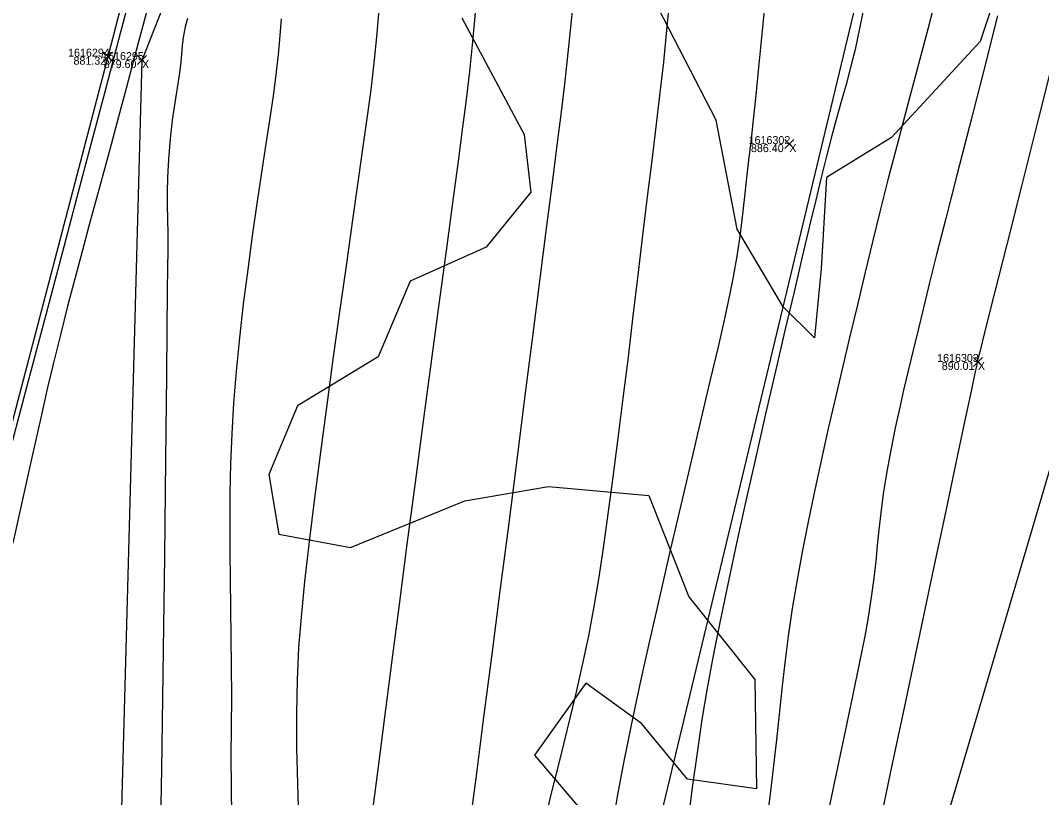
# Model space of a CAD drawing. Extents: x 1957117 to 1971063, y 701601 to 715861.
# Drawn here: x 1963340.46 to 1963385.1, y 706307.76 to 706341.74 of the extents above; entities that cross this region are included whole.
import ezdxf

# ---------------------------------------------------------------- set-up
doc = ezdxf.new("R2010")
doc.units = 0
for name, color, linetype in [('AP_X_Lights', 7, 'Continuous'), ('DT_X_Break_Line', 7, 'Continuous'), ('DT_X_Contour_Major', 7, 'Continuous'), ('DT_X_Contour_Minor', 7, 'Continuous'), ('DT_X_TIN_Hull', 7, 'Continuous'), ('HY_X_Water_Edge', 7, 'Continuous'), ('PV_P_Shoulder', 7, 'Continuous'), ('RS_Raster1', 7, 'Continuous'), ('RW_X_Esmt_RR', 7, 'Continuous'), ('SC_Scratch1', 7, 'Continuous'), ('SC_Shading5', 7, 'Continuous'), ('VG_X_Tree_Line_Rt', 7, 'Continuous')]:
    doc.layers.add(name, color=color, linetype=linetype)

msp = doc.modelspace()

# ---------------------------------------------------------------- linework, layer by layer
at = {"layer": 'AP_X_Lights'}
for p, q in [((1963344.086, 706339.963), (1963344.474, 706340.353)), ((1963344.086, 706340.353), (1963344.474, 706339.963)), ((1963345.578, 706339.814), (1963345.966, 706340.204)), ((1963345.578, 706340.204), (1963345.966, 706339.814)), ((1963373.879, 706336.141), (1963374.267, 706336.531)), ((1963373.879, 706336.531), (1963374.267, 706336.141)), ((1963382.124, 706326.614), (1963382.512, 706327.004)), ((1963382.124, 706327.004), (1963382.512, 706326.614))]:
    msp.add_line(p, q, dxfattribs=at)
at = {"layer": 'DT_X_Break_Line'}
for points in [[(1963218.329, 705756.178), (1963229.265, 705808.356), (1963234.8, 705853.147), (1963240.079, 705903.468), (1963258.033, 705954.684), (1963270.287, 705999.321), (1963276.323, 706049.345), (1963291.502, 706096.678), (1963290.138, 706117.655), (1963319.921, 706191.295), (1963330.374, 706242.631), (1963344.413, 706289.409), (1963345.772, 706340.009), (1963383.117, 706434.704), (1963392.11, 706487.426), (1963408.164, 706535.687), (1963423.633, 706582.721), (1963435.242, 706630.63), (1963443.084, 706680.696), (1963464.732, 706726.815), (1963480.654, 706774.214), (1963508.465, 706799.669), (1963511.002, 706809.48)], [(1963248.355, 705747.376), (1963261.829, 705795.923), (1963267.581, 705840.559), (1963287.153, 705892.264), (1963291.083, 705944.763), (1963301.574, 705996.211), (1963311.528, 706039.027), (1963334.717, 706086.75), (1963331.957, 706106.508), (1963348.786, 706182.796), (1963365.664, 706223.934), (1963373.462, 706281.461), (1963387.853, 706330.217), (1963397.264, 706379.501), (1963407.696, 706427.592), (1963426.755, 706477.16), (1963442.136, 706524.014), (1963446.007, 706569.971), (1963489.391, 706666.839), (1963500.526, 706701.536)]]:
    msp.add_lwpolyline(points, dxfattribs=at)
at = {"layer": 'DT_X_Contour_Major'}
for points in [[(1963368.885, 706343.098), (1963368.724, 706341.474), (1963368.565, 706339.921), (1963368.404, 706338.455), (1963368.241, 706337.093), (1963368.057, 706335.622), (1963367.863, 706334.034), (1963367.661, 706332.355), (1963367.452, 706330.609), (1963367.238, 706328.822), (1963367.021, 706327.02), (1963366.801, 706325.229), (1963366.581, 706323.472), (1963366.362, 706321.777), (1963366.145, 706320.169), (1963365.933, 706318.672), (1963365.727, 706317.313), (1963365.528, 706316.116), (1963365.289, 706314.84), (1963365.035, 706313.618), (1963364.769, 706312.438), (1963364.494, 706311.289), (1963364.214, 706310.158), (1963363.932, 706309.032), (1963363.652, 706307.901), (1963363.377, 706306.752)], [(1963368.885, 706343.098), (1963368.724, 706341.474), (1963368.565, 706339.921), (1963368.404, 706338.455), (1963368.241, 706337.093), (1963368.057, 706335.622), (1963367.863, 706334.034), (1963367.661, 706332.355), (1963367.452, 706330.609), (1963367.238, 706328.822), (1963367.021, 706327.02), (1963366.801, 706325.229), (1963366.581, 706323.472), (1963366.362, 706321.777), (1963366.145, 706320.169), (1963365.933, 706318.672), (1963365.727, 706317.313), (1963365.528, 706316.116), (1963365.289, 706314.84), (1963365.035, 706313.618), (1963364.769, 706312.438), (1963364.494, 706311.289), (1963364.214, 706310.158), (1963363.932, 706309.032), (1963363.652, 706307.901), (1963363.377, 706306.752)], [(1963346.111, 706342.659), (1963345.767, 706341.35), (1963345.421, 706340.044), (1963345.08, 706338.763), (1963344.746, 706337.525), (1963344.418, 706336.319), (1963344.096, 706335.137), (1963343.777, 706333.969), (1963343.462, 706332.805), (1963343.148, 706331.635), (1963342.834, 706330.451), (1963342.52, 706329.242), (1963342.205, 706327.999), (1963341.886, 706326.713), (1963341.645, 706325.695), (1963341.341, 706324.366), (1963340.982, 706322.762), (1963340.575, 706320.921), (1963340.126, 706318.881)], [(1963346.111, 706342.659), (1963345.767, 706341.35), (1963345.421, 706340.044), (1963345.08, 706338.763), (1963344.746, 706337.525), (1963344.418, 706336.319), (1963344.096, 706335.137), (1963343.777, 706333.969), (1963343.462, 706332.805), (1963343.148, 706331.635), (1963342.834, 706330.451), (1963342.52, 706329.242), (1963342.205, 706327.999), (1963341.886, 706326.713), (1963341.645, 706325.695), (1963341.341, 706324.366), (1963340.982, 706322.762), (1963340.575, 706320.921), (1963340.126, 706318.881)], [(1963347.761, 706341.834), (1963347.664, 706341.46), (1963347.575, 706340.998), (1963347.533, 706340.631), (1963347.505, 706340.262), (1963347.456, 706339.79), (1963347.392, 706339.355), (1963347.303, 706338.798), (1963347.201, 706338.137), (1963347.096, 706337.388), (1963347, 706336.565), (1963346.925, 706335.684), (1963346.881, 706334.88), (1963346.868, 706334.224), (1963346.873, 706333.643), (1963346.887, 706333.061), (1963346.897, 706332.404), (1963346.895, 706331.596), (1963346.888, 706331), (1963346.877, 706329.858), (1963346.862, 706328.238), (1963346.841, 706326.204), (1963346.816, 706323.823), (1963346.786, 706321.161), (1963346.752, 706318.282), (1963346.712, 706315.253), (1963346.668, 706312.139), (1963346.619, 706309.006), (1963346.565, 706305.92)], [(1963347.761, 706341.834), (1963347.664, 706341.46), (1963347.575, 706340.998), (1963347.533, 706340.631), (1963347.505, 706340.262), (1963347.456, 706339.79), (1963347.392, 706339.355), (1963347.303, 706338.798), (1963347.201, 706338.137), (1963347.096, 706337.388), (1963347, 706336.565), (1963346.925, 706335.684), (1963346.881, 706334.88), (1963346.868, 706334.224), (1963346.873, 706333.643), (1963346.887, 706333.061), (1963346.897, 706332.404), (1963346.895, 706331.596), (1963346.888, 706331), (1963346.877, 706329.858), (1963346.862, 706328.238), (1963346.841, 706326.204), (1963346.816, 706323.823), (1963346.786, 706321.161), (1963346.752, 706318.282), (1963346.712, 706315.253), (1963346.668, 706312.139), (1963346.619, 706309.006), (1963346.565, 706305.92)], [(1963385.76, 706340.607), (1963384.957, 706337.413), (1963384.224, 706334.501), (1963383.58, 706331.947), (1963383.046, 706329.827), (1963382.641, 706328.218), (1963382.383, 706327.197), (1963382.293, 706326.838), (1963382.275, 706326.757), (1963382.266, 706326.686), (1963382.203, 706326.389), (1963382.022, 706325.538), (1963381.736, 706324.19), (1963381.357, 706322.4), (1963380.897, 706320.226), (1963380.367, 706317.725), (1963379.781, 706314.953), (1963379.151, 706311.967), (1963378.488, 706308.823), (1963377.805, 706305.578)], [(1963385.76, 706340.607), (1963384.957, 706337.413), (1963384.224, 706334.501), (1963383.58, 706331.947), (1963383.046, 706329.827), (1963382.641, 706328.218), (1963382.383, 706327.197), (1963382.293, 706326.838), (1963382.275, 706326.757), (1963382.266, 706326.686), (1963382.203, 706326.389), (1963382.022, 706325.538), (1963381.736, 706324.19), (1963381.357, 706322.4), (1963380.897, 706320.226), (1963380.367, 706317.725), (1963379.781, 706314.953), (1963379.151, 706311.967), (1963378.488, 706308.823), (1963377.805, 706305.578)]]:
    msp.add_lwpolyline(points, dxfattribs=at)
at = {"layer": 'DT_X_Contour_Minor'}
for points in [[(1963339.825, 706322.288), (1963340.689, 706325.546), (1963341.517, 706328.666), (1963342.292, 706331.588), (1963342.999, 706334.255), (1963343.622, 706336.607), (1963344.146, 706338.585), (1963344.555, 706340.131), (1963344.966, 706341.684), (1963345.46, 706343.55)], [(1963339.825, 706322.288), (1963340.689, 706325.546), (1963341.517, 706328.666), (1963342.292, 706331.588), (1963342.999, 706334.255), (1963343.622, 706336.607), (1963344.146, 706338.585), (1963344.555, 706340.131), (1963344.966, 706341.684), (1963345.46, 706343.55)], [(1963364.665, 706343.147), (1963364.529, 706341.725), (1963364.39, 706340.327), (1963364.242, 706338.96), (1963364.084, 706337.632), (1963363.928, 706336.404), (1963363.718, 706334.758), (1963363.463, 706332.755), (1963363.17, 706330.457), (1963362.847, 706327.925), (1963362.501, 706325.221), (1963362.141, 706322.407), (1963361.774, 706319.543), (1963361.408, 706316.691), (1963361.05, 706313.914), (1963360.709, 706311.272), (1963360.392, 706308.826), (1963360.106, 706306.639)], [(1963364.665, 706343.147), (1963364.529, 706341.725), (1963364.39, 706340.327), (1963364.242, 706338.96), (1963364.084, 706337.632), (1963363.928, 706336.404), (1963363.718, 706334.758), (1963363.463, 706332.755), (1963363.17, 706330.457), (1963362.847, 706327.925), (1963362.501, 706325.221), (1963362.141, 706322.407), (1963361.774, 706319.543), (1963361.408, 706316.691), (1963361.05, 706313.914), (1963360.709, 706311.272), (1963360.392, 706308.826), (1963360.106, 706306.639)], [(1963373.064, 706343.105), (1963372.883, 706341.292), (1963372.725, 706339.686), (1963372.59, 706338.332), (1963372.48, 706337.273), (1963372.398, 706336.553), (1963372.286, 706335.635), (1963372.198, 706334.856), (1963372.125, 706334.171), (1963372.056, 706333.532), (1963371.981, 706332.895), (1963371.889, 706332.213), (1963371.772, 706331.439), (1963371.619, 706330.528), (1963371.474, 706329.796), (1963371.249, 706328.766), (1963370.955, 706327.477), (1963370.604, 706325.971), (1963370.208, 706324.287), (1963369.778, 706322.465), (1963369.327, 706320.547), (1963368.865, 706318.573), (1963368.406, 706316.583), (1963367.96, 706314.618), (1963367.539, 706312.717), (1963367.156, 706310.922), (1963366.822, 706309.273), (1963366.549, 706307.811), (1963366.317, 706306.409)], [(1963373.064, 706343.105), (1963372.883, 706341.292), (1963372.725, 706339.686), (1963372.59, 706338.332), (1963372.48, 706337.273), (1963372.398, 706336.553), (1963372.286, 706335.635), (1963372.198, 706334.856), (1963372.125, 706334.171), (1963372.056, 706333.532), (1963371.981, 706332.895), (1963371.889, 706332.213), (1963371.772, 706331.439), (1963371.619, 706330.528), (1963371.474, 706329.796), (1963371.249, 706328.766), (1963370.955, 706327.477), (1963370.604, 706325.971), (1963370.208, 706324.287), (1963369.778, 706322.465), (1963369.327, 706320.547), (1963368.865, 706318.573), (1963368.406, 706316.583), (1963367.96, 706314.618), (1963367.539, 706312.717), (1963367.156, 706310.922), (1963366.822, 706309.273), (1963366.549, 706307.811), (1963366.317, 706306.409)], [(1963380.587, 706343.126), (1963380.123, 706341.362), (1963379.66, 706339.619), (1963379.21, 706337.922), (1963378.781, 706336.298), (1963378.383, 706334.772), (1963378.027, 706333.37), (1963377.722, 706332.119), (1963377.395, 706330.74), (1963377.065, 706329.363), (1963376.736, 706327.989), (1963376.409, 706326.62), (1963376.089, 706325.256), (1963375.776, 706323.901), (1963375.473, 706322.554), (1963375.183, 706321.218), (1963374.907, 706319.893), (1963374.65, 706318.581), (1963374.412, 706317.284), (1963374.203, 706316.025), (1963374.027, 706314.818), (1963373.876, 706313.653), (1963373.744, 706312.518), (1963373.623, 706311.4), (1963373.506, 706310.287), (1963373.387, 706309.169), (1963373.257, 706308.033), (1963373.111, 706306.867)], [(1963380.587, 706343.126), (1963380.123, 706341.362), (1963379.66, 706339.619), (1963379.21, 706337.922), (1963378.781, 706336.298), (1963378.383, 706334.772), (1963378.027, 706333.37), (1963377.722, 706332.119), (1963377.395, 706330.74), (1963377.065, 706329.363), (1963376.736, 706327.989), (1963376.409, 706326.62), (1963376.089, 706325.256), (1963375.776, 706323.901), (1963375.473, 706322.554), (1963375.183, 706321.218), (1963374.907, 706319.893), (1963374.65, 706318.581), (1963374.412, 706317.284), (1963374.203, 706316.025), (1963374.027, 706314.818), (1963373.876, 706313.653), (1963373.744, 706312.518), (1963373.623, 706311.4), (1963373.506, 706310.287), (1963373.387, 706309.169), (1963373.257, 706308.033), (1963373.111, 706306.867)], [(1963356.119, 706342.231), (1963356.032, 706341.177), (1963355.921, 706340.018), (1963355.77, 706338.711), (1963355.631, 706337.662), (1963355.448, 706336.335), (1963355.227, 706334.773), (1963354.978, 706333.018), (1963354.708, 706331.114), (1963354.424, 706329.103), (1963354.135, 706327.029), (1963353.849, 706324.934), (1963353.572, 706322.861), (1963353.313, 706320.853), (1963353.081, 706318.953), (1963352.882, 706317.204), (1963352.725, 706315.648), (1963352.616, 706314.329), (1963352.548, 706312.91), (1963352.522, 706311.434), (1963352.531, 706309.916), (1963352.563, 706308.371), (1963352.61, 706306.815)], [(1963356.119, 706342.231), (1963356.032, 706341.177), (1963355.921, 706340.018), (1963355.77, 706338.711), (1963355.631, 706337.662), (1963355.448, 706336.335), (1963355.227, 706334.773), (1963354.978, 706333.018), (1963354.708, 706331.114), (1963354.424, 706329.103), (1963354.135, 706327.029), (1963353.849, 706324.934), (1963353.572, 706322.861), (1963353.313, 706320.853), (1963353.081, 706318.953), (1963352.882, 706317.204), (1963352.725, 706315.648), (1963352.616, 706314.329), (1963352.548, 706312.91), (1963352.522, 706311.434), (1963352.531, 706309.916), (1963352.563, 706308.371), (1963352.61, 706306.815)], [(1963377.357, 706342.448), (1963377.148, 706341.388), (1963376.948, 706340.48), (1963376.753, 706339.681), (1963376.558, 706338.948), (1963376.359, 706338.238), (1963376.152, 706337.507), (1963375.932, 706336.713), (1963375.695, 706335.811), (1963375.437, 706334.76), (1963375.23, 706333.885), (1963374.961, 706332.755), (1963374.641, 706331.404), (1963374.279, 706329.871), (1963373.884, 706328.191), (1963373.467, 706326.401), (1963373.037, 706324.539), (1963372.604, 706322.641), (1963372.178, 706320.743), (1963371.767, 706318.882), (1963371.382, 706317.096), (1963371.033, 706315.42), (1963370.729, 706313.891), (1963370.48, 706312.547), (1963370.252, 706311.169), (1963370.037, 706309.717), (1963369.832, 706308.205), (1963369.637, 706306.649)], [(1963377.357, 706342.448), (1963377.148, 706341.388), (1963376.948, 706340.48), (1963376.753, 706339.681), (1963376.558, 706338.948), (1963376.359, 706338.238), (1963376.152, 706337.507), (1963375.932, 706336.713), (1963375.695, 706335.811), (1963375.437, 706334.76), (1963375.23, 706333.885), (1963374.961, 706332.755), (1963374.641, 706331.404), (1963374.279, 706329.871), (1963373.884, 706328.191), (1963373.467, 706326.401), (1963373.037, 706324.539), (1963372.604, 706322.641), (1963372.178, 706320.743), (1963371.767, 706318.882), (1963371.382, 706317.096), (1963371.033, 706315.42), (1963370.729, 706313.891), (1963370.48, 706312.547), (1963370.252, 706311.169), (1963370.037, 706309.717), (1963369.832, 706308.205), (1963369.637, 706306.649)], [(1963351.854, 706341.818), (1963351.798, 706341.084), (1963351.725, 706340.249), (1963351.613, 706339.251), (1963351.504, 706338.453), (1963351.36, 706337.477), (1963351.19, 706336.349), (1963351.001, 706335.097), (1963350.799, 706333.745), (1963350.594, 706332.32), (1963350.392, 706330.848), (1963350.201, 706329.354), (1963350.029, 706327.865), (1963349.883, 706326.408), (1963349.771, 706325.007), (1963349.693, 706323.662), (1963349.643, 706322.352), (1963349.616, 706321.068), (1963349.607, 706319.803), (1963349.612, 706318.548), (1963349.626, 706317.297), (1963349.644, 706316.042), (1963349.662, 706314.775), (1963349.675, 706313.488), (1963349.678, 706312.173), (1963349.667, 706310.824), (1963349.66, 706309.552), (1963349.67, 706308.249), (1963349.691, 706306.921)], [(1963351.854, 706341.818), (1963351.798, 706341.084), (1963351.725, 706340.249), (1963351.613, 706339.251), (1963351.504, 706338.453), (1963351.36, 706337.477), (1963351.19, 706336.349), (1963351.001, 706335.097), (1963350.799, 706333.745), (1963350.594, 706332.32), (1963350.392, 706330.848), (1963350.201, 706329.354), (1963350.029, 706327.865), (1963349.883, 706326.408), (1963349.771, 706325.007), (1963349.693, 706323.662), (1963349.643, 706322.352), (1963349.616, 706321.068), (1963349.607, 706319.803), (1963349.612, 706318.548), (1963349.626, 706317.297), (1963349.644, 706316.042), (1963349.662, 706314.775), (1963349.675, 706313.488), (1963349.678, 706312.173), (1963349.667, 706310.824), (1963349.66, 706309.552), (1963349.67, 706308.249), (1963349.691, 706306.921)], [(1963360.34, 706342.098), (1963360.22, 706340.817), (1963360.085, 706339.51), (1963359.927, 706338.172), (1963359.785, 706337.08), (1963359.59, 706335.595), (1963359.348, 706333.774), (1963359.067, 706331.67), (1963358.755, 706329.339), (1963358.421, 706326.835), (1963358.071, 706324.215), (1963357.714, 706321.532), (1963357.357, 706318.841), (1963357.009, 706316.199), (1963356.677, 706313.659), (1963356.369, 706311.276), (1963356.093, 706309.106), (1963355.856, 706307.204)], [(1963360.34, 706342.098), (1963360.22, 706340.817), (1963360.085, 706339.51), (1963359.927, 706338.172), (1963359.785, 706337.08), (1963359.59, 706335.595), (1963359.348, 706333.774), (1963359.067, 706331.67), (1963358.755, 706329.339), (1963358.421, 706326.835), (1963358.071, 706324.215), (1963357.714, 706321.532), (1963357.357, 706318.841), (1963357.009, 706316.199), (1963356.677, 706313.659), (1963356.369, 706311.276), (1963356.093, 706309.106), (1963355.856, 706307.204)], [(1963383.182, 706341.942), (1963382.546, 706339.458), (1963381.946, 706337.118), (1963381.397, 706334.978), (1963380.914, 706333.089), (1963380.512, 706331.508), (1963380.205, 706330.286), (1963380.008, 706329.479), (1963379.733, 706328.327), (1963379.489, 706327.322), (1963379.271, 706326.42), (1963379.071, 706325.581), (1963378.885, 706324.764), (1963378.706, 706323.925), (1963378.527, 706323.025), (1963378.343, 706322.02), (1963378.183, 706321.04), (1963378.068, 706320.206), (1963377.984, 706319.47), (1963377.916, 706318.783), (1963377.849, 706318.095), (1963377.768, 706317.359), (1963377.657, 706316.524), (1963377.503, 706315.542), (1963377.368, 706314.818), (1963377.142, 706313.685), (1963376.835, 706312.192), (1963376.458, 706310.385), (1963376.022, 706308.313), (1963375.538, 706306.024)], [(1963383.182, 706341.942), (1963382.546, 706339.458), (1963381.946, 706337.118), (1963381.397, 706334.978), (1963380.914, 706333.089), (1963380.512, 706331.508), (1963380.205, 706330.286), (1963380.008, 706329.479), (1963379.733, 706328.327), (1963379.489, 706327.322), (1963379.271, 706326.42), (1963379.071, 706325.581), (1963378.885, 706324.764), (1963378.706, 706323.925), (1963378.527, 706323.025), (1963378.343, 706322.02), (1963378.183, 706321.04), (1963378.068, 706320.206), (1963377.984, 706319.47), (1963377.916, 706318.783), (1963377.849, 706318.095), (1963377.768, 706317.359), (1963377.657, 706316.524), (1963377.503, 706315.542), (1963377.368, 706314.818), (1963377.142, 706313.685), (1963376.835, 706312.192), (1963376.458, 706310.385), (1963376.022, 706308.313), (1963375.538, 706306.024)]]:
    msp.add_lwpolyline(points, dxfattribs=at)
at = {"layer": 'DT_X_TIN_Hull'}
msp.add_lwpolyline([(1963495.509, 706817.37), (1963480.654, 706774.214), (1963464.732, 706726.815), (1963443.084, 706680.696), (1963439.989, 706681.954), (1963422.341, 706634.767), (1963409.759, 706587.541), (1963383.299, 706489.662), (1963371.06, 706438.048), (1963369.543, 706438.68), (1963344.28, 706340.158), (1963318.949, 706243.571), (1963307.297, 706195.415), (1963288.342, 706117.136), (1963272.445, 706050.395), (1963261.075, 706002.095), (1963254.734, 705951.873), (1963238.207, 705904.757)], dxfattribs=at)
at = {"layer": 'HY_X_Water_Edge'}
msp.add_spline([(1963191.723, 701994.048), (1963062.047, 702441.167), (1962863.491, 703169.356), (1962827.53, 703438.691), (1962823.213, 703537.412), (1962817.962, 703593.874), (1962817.97, 703697.316), (1962828.582, 703804.235), (1962836.461, 703844.734), (1962850.687, 703896.004), (1962867.251, 703938.846), (1962873.848, 703992.355), (1962884.135, 704091.371), (1962891.241, 704140.854), (1962897.382, 704180.529), (1962905.467, 704230.979), (1962943.949, 704328.022), (1962948.537, 704378.842), (1962964.114, 704426.264), (1963004.885, 704570.73), (1963042.054, 704716.522), (1963062.038, 704814.417), (1963072.171, 704860.237), (1963090.023, 704956.798), (1963107.066, 705031.783), (1963133.773, 705105.742), (1963148.685, 705206.74), (1963175.48, 705301.059), (1963191.635, 705353.417), (1963210.988, 705447.286), (1963219.532, 705497.27), (1963230.124, 705549.475), (1963251.052, 705591.159), (1963275.289, 705693.429), (1963292.982, 705784.032), (1963302.841, 705839.645), (1963335.126, 705936.766), (1963359.752, 706046.75), (1963389.133, 706177.299), (1963417.827, 706273.456), (1963475.868, 706451.902), (1963533.782, 706640.53), (1963553.86, 706696.984), (1963580.184, 706715.425), (1963609.172, 706718.73), (1963617.062, 706714.691), (1963619.447, 706694.678), (1963564.282, 706533.07), (1963531.853, 706395.229), (1963434.4, 706006.96), (1963354.09, 705679.186), (1963237.513, 705206.07), (1963167.369, 704892.962), (1963059.145, 704434.176), (1962907.914, 703908.742), (1962877.458, 703703.326), (1962898.357, 703412.121), (1962942.65, 703052.267), (1963048.963, 702674.866), (1963191.468, 702189.666), (1963245.396, 702019.832)], degree=3, dxfattribs=at)
at = {"layer": 'RW_X_Esmt_RR'}
msp.add_lwpolyline([(1962866.45, 704268.068), (1963123.345, 705337.727), (1963135.496, 705336.937), (1963400.797, 706441.601)], dxfattribs=at)
at = {"layer": 'SC_Shading5'}
for points in [[(1963026.912, 704294.121), (1963138.818, 704737.794), (1963251.679, 705213.963), (1963374.306, 705730.111), (1963454.783, 706045.593), (1963517.244, 706296.713), (1963562.763, 706479.256), (1963580.13, 706553.799), (1963589.678, 706586.994)], [(1963609.915, 706579.703), (1963587.283, 706499.153), (1963552.056, 706354.005), (1963480.911, 706069.234), (1963357.401, 705576.869), (1963272.751, 705226.931), (1963210.247, 704956.481), (1963044.97, 704288.881)]]:
    msp.add_spline(points, degree=3, dxfattribs=at)
at = {"layer": 'VG_X_Tree_Line_Rt'}
for points in [[(1963383.506, 706344.111), (1963382.422, 706340.817), (1963378.545, 706336.626), (1963375.7, 706334.874), (1963375.467, 706330.898), (1963375.173, 706327.862), (1963373.802, 706329.223), (1963371.798, 706332.619), (1963370.881, 706337.38), (1963367.45, 706344.033)], [(1963359.761, 706341.863), (1963362.474, 706336.763), (1963362.775, 706334.23), (1963360.822, 706331.831), (1963357.496, 706330.336), (1963356.098, 706327.034), (1963352.566, 706324.888), (1963351.315, 706321.887), (1963351.754, 706319.274), (1963354.894, 706318.698), (1963359.879, 706320.739), (1963363.543, 706321.369), (1963367.931, 706320.971), (1963369.676, 706316.542), (1963372.571, 706312.926), (1963372.64, 706308.144), (1963369.626, 706308.561), (1963367.605, 706310.997), (1963365.181, 706312.76), (1963362.931, 706309.611), (1963365.016, 706307.169), (1963365.266, 706304.442)]]:
    msp.add_lwpolyline(points, dxfattribs=at)

# ---------------------------------------------------------------- texts
at = {"layer": 'PV_P_Shoulder'}
for s, p in [('881.32', (1963342.776, 706339.808)), ('879.60', (1963344.097, 706339.659)), ('886.40', (1963372.395, 706335.986)), ('890.01', (1963380.738, 706326.459))]:
    msp.add_text(s, height=0.35, dxfattribs=at).set_placement(p)
at = {"layer": 'RS_Raster1'}
for s, p in [('1616294', (1963342.539, 706340.158)), ('1616295', (1963344.028, 706340.009)), ('1616302', (1963372.293, 706336.336)), ('1616303', (1963380.535, 706326.809))]:
    msp.add_text(s, height=0.35, dxfattribs=at).set_placement(p)
at = {"layer": 'SC_Scratch1'}
for p in [(1963344.28, 706339.808), (1963345.772, 706339.659), (1963374.073, 706335.986), (1963382.318, 706326.459)]:
    msp.add_text('X', height=0.35, dxfattribs=at).set_placement(p)

doc.saveas('drawing.dxf')
